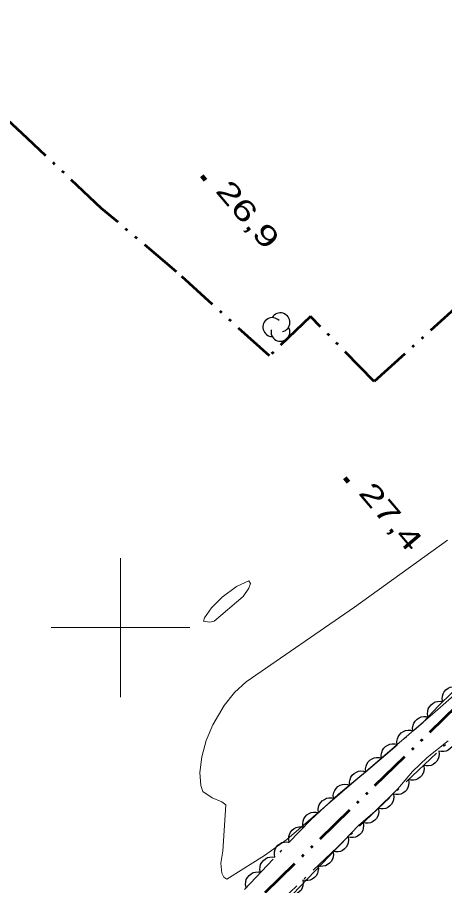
# Model space of a CAD drawing. Extents: x 386081 to 389416, y 5130568 to 5134082.
# Drawn here: x 388385.1 to 388446.7, y 5131762.8 to 5131887.9 of the extents above; entities that cross this region are included whole.
import ezdxf

# ---------------------------------------------------------------- set-up
doc = ezdxf.new("R2010")
doc.units = 0
doc.header["$LTSCALE"] = 1.2
doc.linetypes.add('DASH_DOUBLE_DOT', pattern=[9.2, 5, -1.2, 0.3, -1.2, 0.3, -1.2])
doc.linetypes.add('DOT_DASHED', pattern=[7.7, 5, -1.2, 0.3, -1.2])
for name, color, linetype, lineweight in [('2', 7, 'Continuous', 13), ('3', 7, 'Continuous', 140), ('4', 7, 'DASH_DOUBLE_DOT', 53), ('44', 7, 'Continuous', 25), ('61', 7, 'Continuous', 13)]:
    doc.layers.add(name, color=color, linetype=linetype, lineweight=lineweight)

msp = doc.modelspace()

# ---------------------------------------------------------------- linework, layer by layer
at = {"layer": '2'}
for points in [[(388459.82, 5131800.53), (388445.36, 5131787.86), (388423.96, 5131769.49), (388420.74, 5131767.15), (388415.32, 5131763.78), (388414.88, 5131764.03), (388414.59, 5131764.62), (388414.47, 5131766.09), (388414.73, 5131767.79), (388415.2, 5131774.48), (388414.62, 5131774.91), (388413.19, 5131775.49), (388411.89, 5131776.38), (388411.57, 5131777.26), (388411.44, 5131779.12), (388411.71, 5131781.36), (388412.34, 5131783.72), (388413.31, 5131785.97), (388414.95, 5131788.78), (388416.43, 5131790.63), (388418.11, 5131792.19), (388433.73, 5131802.92), (388447.14, 5131812.58)], [(388424.84, 5131761.59), (388434.28, 5131771.51), (388436.69, 5131773.55), (388439.95, 5131776.76), (388442.06, 5131779.29), (388444.21, 5131781.3), (388447.21, 5131783.71)]]:
    msp.add_lwpolyline(points, dxfattribs=at)
msp.add_lwpolyline([(388413.51, 5131800.94), (388412.84, 5131800.76), (388411.95, 5131800.9), (388412.11, 5131801.41), (388413.13, 5131802.84), (388414.66, 5131804.38), (388416.73, 5131805.9), (388418.48, 5131806.75), (388418.72, 5131806.34), (388418.48, 5131805.69), (388417.66, 5131804.48)], close=True, dxfattribs=at)
at = {"layer": '3'}
for p, q in [((388411.74, 5131865.07), (388412.25, 5131864.46)), ((388432.35, 5131821.56), (388432.86, 5131820.95))]:
    msp.add_line(p, q, dxfattribs=at)
at = {"layer": '4'}
for points in [[(388403.08, 5131676.15), (388398.8, 5131683.5), (388385.24, 5131705.68), (388376.19, 5131718.23), (388378.12, 5131720.75), (388380.58, 5131723.47), (388405.01, 5131746.47), (388448.58, 5131788.82), (388515.07, 5131852.58), (388524.6, 5131861.96), (388550.41, 5131886.49), (388583.66, 5131918.46), (388613.94, 5131948.36), (388649.63, 5131983.32), (388677.59, 5132010.13), (388707.98, 5132038.7), (388732.5, 5132062.17)], [(388459.35, 5131838.68), (388456.93, 5131841.01), (388453.18, 5131843.53), (388449.14, 5131846.84), (388436.56, 5131835.45), (388427.39, 5131844.82), (388421.46, 5131839.12), (388408.07, 5131851.24), (388397.28, 5131860.38), (388386.58, 5131870.47), (388380.49, 5131876.08), (388377.26, 5131879.24), (388374.53, 5131881.51)]]:
    msp.add_lwpolyline(points, dxfattribs=at)
at = {"layer": '44', "linetype": 'DOT_DASHED'}
for points in [[(388492.44, 5131826.41), (388403.12, 5131741.66)], [(388417.85, 5131762.29), (388427.41, 5131772.3), (388431.43, 5131776.01), (388435.33, 5131779.2), (388443.61, 5131786.38), (388445.87, 5131788.76), (388453.46, 5131796.25)]]:
    msp.add_lwpolyline(points, dxfattribs=at)
at = {"layer": '44'}
for points in [[(388446.43, 5131789.32), (388446.36, 5131789.73), (388446.4, 5131790.13), (388446.48, 5131790.45), (388446.66, 5131790.75), (388446.9, 5131791.04), (388447.21, 5131791.26), (388447.5, 5131791.41), (388447.84, 5131791.48), (388448.22, 5131791.49), (388448.57, 5131791.42)], [(388444.35, 5131787.16), (388444.26, 5131787.57), (388444.29, 5131787.97), (388444.36, 5131788.29), (388444.53, 5131788.6), (388444.76, 5131788.89), (388445.07, 5131789.12), (388445.35, 5131789.29), (388445.69, 5131789.37), (388446.06, 5131789.39), (388446.41, 5131789.33)], [(388442.15, 5131785.12), (388442.1, 5131785.53), (388442.18, 5131785.93), (388442.28, 5131786.25), (388442.47, 5131786.54), (388442.73, 5131786.8), (388443.06, 5131787), (388443.35, 5131787.14), (388443.7, 5131787.19), (388444.07, 5131787.18), (388444.42, 5131787.08)], [(388439.89, 5131783.15), (388439.84, 5131783.57), (388439.91, 5131783.97), (388440.01, 5131784.28), (388440.21, 5131784.57), (388440.46, 5131784.84), (388440.79, 5131785.04), (388441.09, 5131785.18), (388441.44, 5131785.22), (388441.81, 5131785.21), (388442.15, 5131785.12)], [(388448.03, 5131784.28), (388448.1, 5131783.86), (388448.05, 5131783.46), (388447.96, 5131783.14), (388447.78, 5131782.84), (388447.53, 5131782.57), (388447.22, 5131782.35), (388446.93, 5131782.2), (388446.58, 5131782.14), (388446.21, 5131782.13), (388445.86, 5131782.21)], [(388437.62, 5131781.19), (388437.57, 5131781.6), (388437.64, 5131782), (388437.74, 5131782.32), (388437.94, 5131782.61), (388438.2, 5131782.87), (388438.53, 5131783.07), (388438.82, 5131783.21), (388439.17, 5131783.26), (388439.54, 5131783.25), (388439.89, 5131783.15)], [(388445.86, 5131782.21), (388445.93, 5131781.8), (388445.87, 5131781.4), (388445.79, 5131781.08), (388445.6, 5131780.78), (388445.36, 5131780.5), (388445.04, 5131780.29), (388444.75, 5131780.13), (388444.4, 5131780.07), (388444.03, 5131780.07), (388443.68, 5131780.15)], [(388435.35, 5131779.22), (388435.31, 5131779.64), (388435.38, 5131780.04), (388435.48, 5131780.35), (388435.67, 5131780.64), (388435.93, 5131780.91), (388436.26, 5131781.11), (388436.55, 5131781.25), (388436.9, 5131781.29), (388437.27, 5131781.28), (388437.62, 5131781.19)], [(388443.68, 5131780.15), (388443.75, 5131779.73), (388443.7, 5131779.33), (388443.61, 5131779.01), (388443.43, 5131778.71), (388443.18, 5131778.44), (388442.86, 5131778.22), (388442.57, 5131778.07), (388442.23, 5131778.01), (388441.86, 5131778), (388441.5, 5131778.08)], [(388433.03, 5131777.32), (388433, 5131777.74), (388433.08, 5131778.14), (388433.19, 5131778.45), (388433.39, 5131778.73), (388433.66, 5131778.99), (388433.99, 5131779.18), (388434.29, 5131779.31), (388434.64, 5131779.35), (388435.01, 5131779.32), (388435.36, 5131779.22)], [(388430.71, 5131775.42), (388430.67, 5131775.84), (388430.76, 5131776.24), (388430.87, 5131776.55), (388431.07, 5131776.83), (388431.34, 5131777.09), (388431.67, 5131777.28), (388431.97, 5131777.41), (388432.32, 5131777.45), (388432.69, 5131777.42), (388433.03, 5131777.32)], [(388441.5, 5131778.08), (388441.57, 5131777.67), (388441.52, 5131777.27), (388441.43, 5131776.95), (388441.25, 5131776.65), (388441, 5131776.37), (388440.69, 5131776.16), (388440.4, 5131776), (388440.05, 5131775.94), (388439.68, 5131775.94), (388439.33, 5131776.02)], [(388439.33, 5131776.02), (388439.4, 5131775.6), (388439.34, 5131775.2), (388439.26, 5131774.88), (388439.07, 5131774.58), (388438.83, 5131774.31), (388438.51, 5131774.09), (388438.22, 5131773.94), (388437.87, 5131773.88), (388437.5, 5131773.87), (388437.15, 5131773.95)], [(388428.54, 5131773.35), (388428.48, 5131773.76), (388428.54, 5131774.16), (388428.63, 5131774.48), (388428.82, 5131774.78), (388429.07, 5131775.05), (388429.39, 5131775.26), (388429.68, 5131775.41), (388430.03, 5131775.46), (388430.4, 5131775.46), (388430.75, 5131775.38)], [(388426.34, 5131771.31), (388426.28, 5131771.72), (388426.33, 5131772.13), (388426.42, 5131772.44), (388426.61, 5131772.74), (388426.86, 5131773.01), (388427.18, 5131773.22), (388427.47, 5131773.37), (388427.82, 5131773.43), (388428.19, 5131773.43), (388428.54, 5131773.35)], [(388437.15, 5131773.95), (388437.22, 5131773.54), (388437.17, 5131773.14), (388437.08, 5131772.82), (388436.9, 5131772.52), (388436.65, 5131772.24), (388436.33, 5131772.03), (388436.05, 5131771.88), (388435.7, 5131771.81), (388435.33, 5131771.81), (388434.98, 5131771.89)], [(388424.33, 5131769.08), (388424.24, 5131769.48), (388424.28, 5131769.89), (388424.35, 5131770.21), (388424.52, 5131770.52), (388424.75, 5131770.81), (388425.05, 5131771.04), (388425.33, 5131771.2), (388425.68, 5131771.28), (388426.05, 5131771.31), (388426.4, 5131771.25)], [(388434.98, 5131771.89), (388435.04, 5131771.47), (388434.99, 5131771.07), (388434.91, 5131770.75), (388434.72, 5131770.45), (388434.48, 5131770.18), (388434.16, 5131769.96), (388433.87, 5131769.81), (388433.52, 5131769.75), (388433.15, 5131769.74), (388432.8, 5131769.82)], [(388432.8, 5131769.82), (388432.87, 5131769.41), (388432.82, 5131769.01), (388432.73, 5131768.69), (388432.54, 5131768.39), (388432.3, 5131768.11), (388431.98, 5131767.9), (388431.69, 5131767.75), (388431.35, 5131767.68), (388430.98, 5131767.68), (388430.62, 5131767.76)], [(388422.26, 5131766.91), (388422.17, 5131767.31), (388422.2, 5131767.72), (388422.27, 5131768.04), (388422.44, 5131768.35), (388422.67, 5131768.64), (388422.98, 5131768.87), (388423.26, 5131769.03), (388423.61, 5131769.11), (388423.98, 5131769.14), (388424.33, 5131769.08)], [(388430.62, 5131767.76), (388430.69, 5131767.34), (388430.64, 5131766.94), (388430.55, 5131766.62), (388430.37, 5131766.32), (388430.12, 5131766.05), (388429.8, 5131765.83), (388429.52, 5131765.68), (388429.17, 5131765.62), (388428.8, 5131765.61), (388428.45, 5131765.69)], [(388420.19, 5131764.74), (388420.1, 5131765.15), (388420.13, 5131765.55), (388420.2, 5131765.87), (388420.37, 5131766.18), (388420.6, 5131766.47), (388420.91, 5131766.7), (388421.19, 5131766.86), (388421.53, 5131766.94), (388421.9, 5131766.97), (388422.26, 5131766.91)], [(388418.11, 5131762.57), (388418.03, 5131762.98), (388418.06, 5131763.38), (388418.13, 5131763.7), (388418.3, 5131764.01), (388418.53, 5131764.3), (388418.84, 5131764.53), (388419.12, 5131764.7), (388419.46, 5131764.77), (388419.83, 5131764.8), (388420.19, 5131764.74)], [(388428.45, 5131765.69), (388428.52, 5131765.28), (388428.46, 5131764.88), (388428.38, 5131764.56), (388428.19, 5131764.26), (388427.95, 5131763.98), (388427.63, 5131763.77), (388427.34, 5131763.62), (388426.99, 5131763.55), (388426.62, 5131763.55), (388426.27, 5131763.63)], [(388426.27, 5131763.63), (388426.34, 5131763.21), (388426.29, 5131762.81), (388426.2, 5131762.49), (388426.02, 5131762.19), (388425.77, 5131761.92), (388425.45, 5131761.7), (388425.16, 5131761.55), (388424.82, 5131761.49), (388424.45, 5131761.48), (388424.09, 5131761.56)]]:
    msp.add_lwpolyline(points, dxfattribs=at)
for centre, start, end in [((388423.048, 5131843.961), 282.26917, 149.72626), ((388421.878, 5131843.281), 44.11537, 269.80396), ((388423.048, 5131842.601), 166.93686, 29.62122)]:
    msp.add_arc(centre, 1.36, start, end, dxfattribs=at)
at = {"layer": '61'}
for p, q in [((388400, 5131790), (388400, 5131810)), ((388390, 5131800), (388410, 5131800))]:
    msp.add_line(p, q, dxfattribs=at)

# ---------------------------------------------------------------- texts
at = {"layer": '3', "width": 1.45}
for s, p in [('26,9   ', (388413.57, 5131862.85)), ('27,4   ', (388434.18, 5131819.34))]:
    msp.add_text(s, height=3, rotation=310.294, dxfattribs=at).set_placement(p)

doc.saveas('drawing.dxf')
